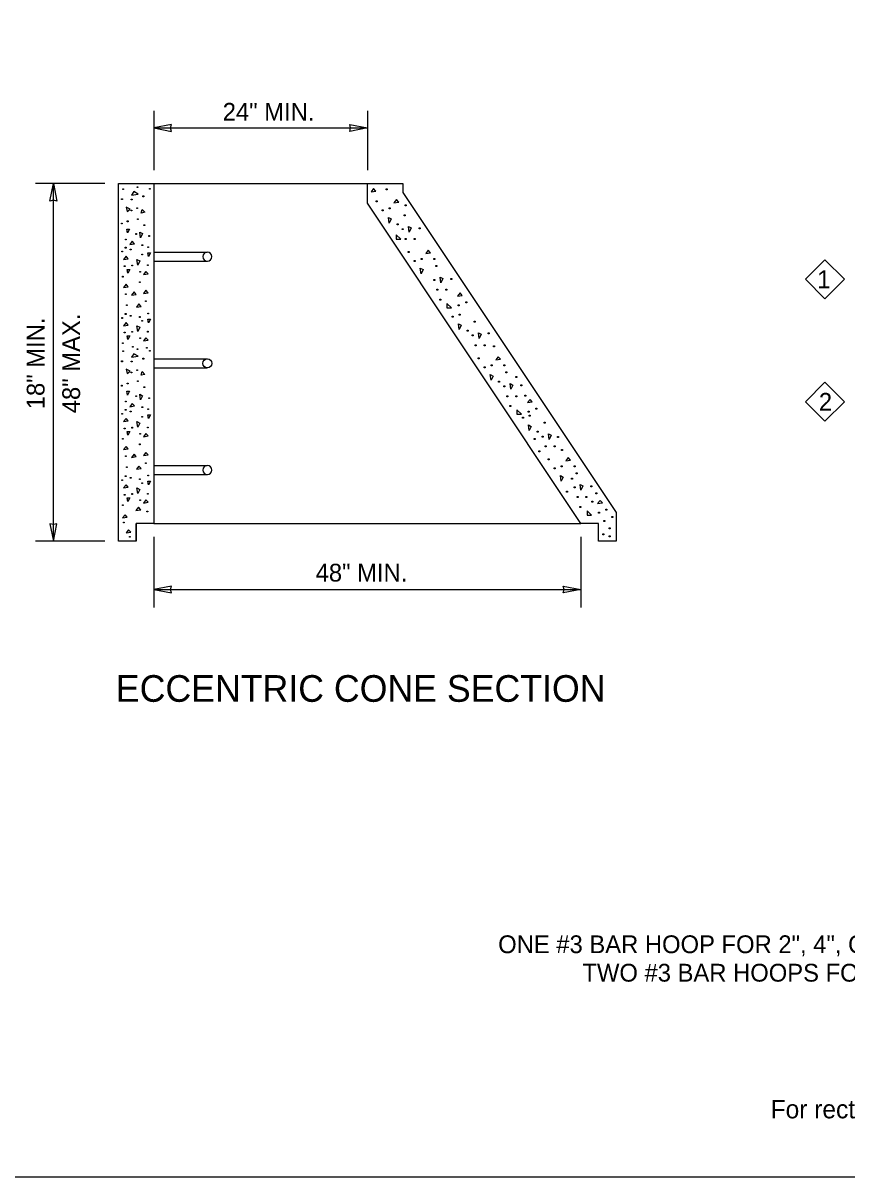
# Model space of a CAD drawing. Extents: x 99862 to 103151, y 100000 to 102076.
# Drawn here: x 100987 to 101728, y 100000 to 101038 of the extents above; entities that cross this region are included whole.
import ezdxf

# ---------------------------------------------------------------- set-up
doc = ezdxf.new("R2010")
doc.units = 0
for name, color, linetype in [('Level 1', 7, 'Continuous'), ('Level 15', 7, 'Continuous'), ('Level 17', 7, 'Continuous'), ('Level 18', 7, 'Continuous'), ('Level 20', 7, 'Continuous')]:
    doc.layers.add(name, color=color, linetype=linetype)

msp = doc.modelspace()

# ---------------------------------------------------------------- linework, layer by layer
at = {"layer": 'Level 1'}
for p, q in [((101086.4, 100885.9), (101084.4, 100882.7)), ((101084.4, 100882.7), (101090.5, 100883.6)), ((101090.5, 100883.6), (101086.4, 100885.9)), ((101079.7, 100872), (101080.6, 100868)), ((101083.3, 100870.2), (101079.7, 100872)), ((101080.6, 100868), (101083.3, 100870.2)), ((101093.1, 100866.6), (101094, 100869.8)), ((101096.3, 100867.3), (101093.1, 100866.6)), ((101094, 100869.8), (101096.3, 100867.3)), ((101086.4, 100740), (101084.4, 100736.9)), ((101090.5, 100737.8), (101086.4, 100740)), ((101084.4, 100736.9), (101090.5, 100737.8)), ((101079.7, 100726.2), (101080.6, 100722.2)), ((101083.3, 100724.4), (101079.7, 100726.2)), ((101080.6, 100722.2), (101083.3, 100724.4)), ((101093.1, 100720.8), (101094, 100724)), ((101096.3, 100721.5), (101093.1, 100720.8)), ((101094, 100724), (101096.3, 100721.5)), ((101104.6, 100527.9), (101488.6, 100527.9))]:
    msp.add_line(p, q, dxfattribs=at)
for points in [[(99862, 99999.5), (103151, 99999.5), (103151, 102075.5), (99862, 102075.5)], [(101076.6, 100888.5), (101077.3, 100888.5), (101077.3, 100887.9), (101076.6, 100887.9)], [(101089.6, 100890.3), (101090.2, 100890.3), (101090.2, 100889.7), (101089.6, 100889.7)], [(101100.5, 100888.8), (101101.2, 100888.8), (101101.2, 100888.1), (101100.5, 100888.1)], [(101302.2, 100888.6), (101299.9, 100885.7), (101304.2, 100886.3)], [(101313.6, 100888.3), (101314.5, 100888.3), (101314.5, 100887.4), (101313.6, 100887.4)], [(101075.5, 100879.4), (101076.2, 100879.4), (101076.2, 100878.7), (101075.5, 100878.7)], [(101084.2, 100879.2), (101084.9, 100879.2), (101084.9, 100878.5), (101084.2, 100878.5)], [(101094.5, 100882.1), (101095.4, 100882.1), (101095.4, 100881.2), (101094.5, 100881.2)], [(101304.6, 100877.6), (101305.5, 100877.6), (101305.5, 100876.7), (101304.6, 100876.7)], [(101322.7, 100878.7), (101320.5, 100875.8), (101324.8, 100876.5)], [(101330.6, 100874), (101331.4, 100874), (101331.4, 100873.1), (101330.6, 100873.1)], [(101084, 100869.3), (101084.6, 100869.3), (101084.6, 100868.7), (101084, 100868.7)], [(101089.1, 100871.3), (101089.8, 100871.3), (101089.8, 100870.7), (101089.1, 100870.7)], [(101310, 100869.5), (101310.9, 100869.5), (101310.9, 100868.6), (101310, 100868.6)], [(101315.6, 100862.6), (101318, 100861.3), (101316.3, 100857.5)], [(101316.2, 100871.3), (101317.1, 100871.3), (101317.1, 100870.4), (101316.2, 100870.4)], [(101329.7, 100865.1), (101330.6, 100865.1), (101330.6, 100864.2), (101329.7, 100864.2)], [(101075.3, 100857.5), (101075.9, 100857.5), (101075.9, 100856.8), (101075.3, 100856.8)], [(101080.2, 100852.1), (101082.6, 100852.1), (101080.8, 100848.8)], [(101080.6, 100859.5), (101081.3, 100859.5), (101081.3, 100858.8), (101080.6, 100858.8)], [(101089.8, 100861.5), (101090.5, 100861.5), (101090.5, 100860.8), (101089.8, 100860.8)], [(101095.6, 100856.1), (101096.3, 100856.1), (101096.3, 100855.5), (101095.6, 100855.5)], [(101323.4, 100857), (101324.3, 100857), (101324.3, 100856.1), (101323.4, 100856.1)], [(101327.9, 100852.5), (101328.8, 100852.5), (101328.8, 100851.7), (101327.9, 100851.7)], [(101333.5, 100854.6), (101335.9, 100853.2), (101334.1, 100849.4)], [(101343.1, 100853.4), (101344, 100853.4), (101344, 100852.5), (101343.1, 100852.5)], [(101079.1, 100843.2), (101079.7, 100843.2), (101079.7, 100842.5), (101079.1, 100842.5)], [(101088.2, 100848.1), (101088.9, 100848.1), (101088.9, 100847.4), (101088.2, 100847.4)], [(101091.8, 100849.4), (101094.3, 100848.1), (101092.5, 100844.3)], [(101100.1, 100846.3), (101100.7, 100846.3), (101100.7, 100845.6), (101100.1, 100845.6)], [(101322.6, 100847), (101322.6, 100843), (101326.6, 100843)], [(101330.6, 100843.6), (101331.5, 100843.6), (101331.5, 100842.7), (101330.6, 100842.7)], [(101338.6, 100843.6), (101339.5, 100843.6), (101339.5, 100842.7), (101338.6, 100842.7)], [(101075.7, 100832.2), (101076.4, 100832.2), (101076.4, 100831.6), (101075.7, 100831.6)], [(101078.8, 100835.8), (101079.5, 100835.8), (101079.5, 100835.1), (101078.8, 100835.1)], [(101085.1, 100841.2), (101082.9, 100838.3), (101087.1, 100838.9)], [(101083.3, 100834.2), (101084, 100834.2), (101084, 100833.6), (101083.3, 100833.6)], [(101093.8, 100838), (101094.5, 100838), (101094.5, 100837.4), (101093.8, 100837.4)], [(101099.2, 100836.3), (101099.8, 100836.3), (101099.8, 100835.6), (101099.2, 100835.6)], [(101333.2, 100832), (101334.1, 100832), (101334.1, 100831.1), (101333.2, 100831.1)], [(101351.4, 100833.1), (101349.1, 100830.2), (101353.4, 100830.9)], [(101079.5, 100827.8), (101077.3, 100824.9), (101081.5, 100825.5)], [(101089.3, 100824.9), (101091.8, 100823.5), (101090, 100819.7)], [(101093.6, 100829.5), (101094.3, 100829.5), (101094.3, 100828.9), (101093.6, 100828.9)], [(101099.2, 100830.9), (101101.6, 100830.9), (101099.8, 100827.5)], [(101338.6, 100823.9), (101339.5, 100823.9), (101339.5, 100823), (101338.6, 100823)], [(101344.9, 100825.7), (101345.8, 100825.7), (101345.8, 100824.8), (101344.9, 100824.8)], [(101356.5, 100825.7), (101357.4, 100825.7), (101357.4, 100824.8), (101356.5, 100824.8)], [(101077.9, 100819), (101078.6, 100819), (101078.6, 100818.4), (101077.9, 100818.4)], [(101080.4, 100815.9), (101082.9, 100815.9), (101081.1, 100812.6)], [(101084.6, 100819.7), (101085.3, 100819.7), (101085.3, 100819), (101084.6, 100819)], [(101091.8, 100814.1), (101092.5, 100814.1), (101092.5, 100813.5), (101091.8, 100813.5)], [(101097.4, 100814.1), (101095.2, 100811.2), (101099.4, 100811.9)], [(101098.7, 100819.9), (101099.4, 100819.9), (101099.4, 100819.3), (101098.7, 100819.3)], [(101344.2, 100817), (101346.7, 100815.7), (101344.9, 100811.9)], [(101358.3, 100819.5), (101359.2, 100819.5), (101359.2, 100818.6), (101358.3, 100818.6)], [(101076.4, 100809.7), (101077, 100809.7), (101077, 100809), (101076.4, 100809)], [(101079.5, 100802.5), (101077.3, 100799.6), (101081.5, 100800.3)], [(101091.6, 100804.7), (101092.2, 100804.7), (101092.2, 100804), (101091.6, 100804)], [(101356.5, 100806.9), (101357.4, 100806.9), (101357.4, 100806), (101356.5, 100806)], [(101362.1, 100808.9), (101364.5, 100807.6), (101362.8, 100803.8)], [(101371.7, 100807.8), (101372.6, 100807.8), (101372.6, 100806.9), (101371.7, 100806.9)], [(101079.1, 100793.9), (101079.7, 100793.9), (101079.7, 100793.3), (101079.1, 100793.3)], [(101086.7, 100795.6), (101084.4, 100792.7), (101088.7, 100793.3)], [(101097.4, 100797.1), (101095.2, 100794.2), (101099.4, 100794.9)], [(101359.2, 100798), (101360.1, 100798), (101360.1, 100797.1), (101359.2, 100797.1)], [(101367.2, 100798), (101368.1, 100798), (101368.1, 100797.1), (101367.2, 100797.1)], [(101380, 100794.7), (101377.7, 100791.8), (101382, 100792.4)], [(101080, 100784.1), (101080.6, 100784.1), (101080.6, 100783.4), (101080, 100783.4)], [(101091.1, 100784.8), (101088.9, 100781.9), (101093.1, 100782.6)], [(101096.9, 100787.7), (101097.6, 100787.7), (101097.6, 100787), (101096.9, 100787)], [(101361.9, 100789.1), (101362.8, 100789.1), (101362.8, 100788.2), (101361.9, 100788.2)], [(101368.2, 100785.3), (101368.2, 100781.3), (101372.2, 100781.3)], [(101378.4, 100784.1), (101379.3, 100784.1), (101379.3, 100783.2), (101378.4, 100783.2)], [(101385.1, 100786.8), (101386, 100786.8), (101386, 100785.9), (101385.1, 100785.9)], [(101075.7, 100772.5), (101076.4, 100772.5), (101076.4, 100771.8), (101075.7, 100771.8)], [(101078.8, 100776.1), (101079.5, 100776.1), (101079.5, 100775.4), (101078.8, 100775.4)], [(101083.3, 100774.5), (101084, 100774.5), (101084, 100773.9), (101083.3, 100773.9)], [(101091.6, 100773.4), (101092.2, 100773.4), (101092.2, 100772.7), (101091.6, 100772.7)], [(101093.6, 100769.8), (101094.3, 100769.8), (101094.3, 100769.2), (101093.6, 100769.2)], [(101099.2, 100776.5), (101099.8, 100776.5), (101099.8, 100775.9), (101099.2, 100775.9)], [(101099.2, 100771.2), (101101.6, 100771.2), (101099.8, 100767.8)], [(101373, 100773.9), (101373.9, 100773.9), (101373.9, 100773), (101373, 100773)], [(101379.3, 100775.6), (101380.2, 100775.6), (101380.2, 100774.7), (101379.3, 100774.7)], [(101392.7, 100769.4), (101393.6, 100769.4), (101393.6, 100768.5), (101392.7, 100768.5)], [(101079.5, 100768), (101077.3, 100765.1), (101081.5, 100765.8)], [(101077.9, 100759.3), (101078.6, 100759.3), (101078.6, 100758.7), (101077.9, 100758.7)], [(101084.6, 100760), (101085.3, 100760), (101085.3, 100759.3), (101084.6, 100759.3)], [(101089.3, 100765.1), (101091.8, 100763.8), (101090, 100760)], [(101098.7, 100760.2), (101099.4, 100760.2), (101099.4, 100759.5), (101098.7, 100759.5)], [(101378.6, 100766.9), (101381.1, 100765.6), (101379.3, 100761.8)], [(101386.4, 100761.3), (101387.3, 100761.3), (101387.3, 100760.4), (101386.4, 100760.4)], [(101396.5, 100758.9), (101399, 100757.5), (101397.2, 100753.7)], [(101405.2, 100758.7), (101406.1, 100758.7), (101406.1, 100757.8), (101405.2, 100757.8)], [(101076.4, 100749.9), (101077, 100749.9), (101077, 100749.3), (101076.4, 100749.3)], [(101080.4, 100756.2), (101082.9, 100756.2), (101081.1, 100752.8)], [(101091.8, 100754.4), (101092.5, 100754.4), (101092.5, 100753.7), (101091.8, 100753.7)], [(101097.4, 100754.4), (101095.2, 100751.5), (101099.4, 100752.2)], [(101390.9, 100756.9), (101391.8, 100756.9), (101391.8, 100756), (101390.9, 100756)], [(101076.6, 100742.7), (101077.3, 100742.7), (101077.3, 100742.1), (101076.6, 100742.1)], [(101085.3, 100746.5), (101086, 100746.5), (101086, 100745.9), (101085.3, 100745.9)], [(101089.6, 100744.5), (101090.2, 100744.5), (101090.2, 100743.8), (101089.6, 100743.8)], [(101097.8, 100745.6), (101098.5, 100745.6), (101098.5, 100745), (101097.8, 100745)], [(101100.5, 100742.9), (101101.2, 100742.9), (101101.2, 100742.3), (101100.5, 100742.3)], [(101393.6, 100747.9), (101394.5, 100747.9), (101394.5, 100747), (101393.6, 100747)], [(101401.7, 100747.9), (101402.6, 100747.9), (101402.6, 100747), (101401.7, 100747)], [(101410.2, 100747), (101411, 100747), (101411, 100746.1), (101410.2, 100746.1)], [(101075.5, 100733.6), (101076.2, 100733.6), (101076.2, 100732.9), (101075.5, 100732.9)], [(101084.2, 100733.3), (101084.9, 100733.3), (101084.9, 100732.7), (101084.2, 100732.7)], [(101094.5, 100736.2), (101095.4, 100736.2), (101095.4, 100735.3), (101094.5, 100735.3)], [(101396.3, 100736.3), (101397.2, 100736.3), (101397.2, 100735.4), (101396.3, 100735.4)], [(101401.6, 100728.2), (101402.5, 100728.2), (101402.5, 100727.3), (101401.6, 100727.3)], [(101407.9, 100730), (101408.8, 100730), (101408.8, 100729.1), (101407.9, 100729.1)], [(101414.4, 100737.4), (101412.2, 100734.5), (101416.4, 100735.2)], [(101419.5, 100730), (101420.4, 100730), (101420.4, 100729.1), (101419.5, 100729.1)], [(101084, 100723.5), (101084.6, 100723.5), (101084.6, 100722.8), (101084, 100722.8)], [(101089.1, 100725.5), (101089.8, 100725.5), (101089.8, 100724.9), (101089.1, 100724.9)], [(101407.2, 100721.3), (101409.7, 100720), (101407.9, 100716.2)], [(101421.3, 100723.8), (101422.2, 100723.8), (101422.2, 100722.9), (101421.3, 100722.9)], [(101430.3, 100719.7), (101431.2, 100719.7), (101431.2, 100718.8), (101430.3, 100718.8)], [(101075.3, 100711.7), (101075.9, 100711.7), (101075.9, 100711), (101075.3, 100711)], [(101080.6, 100713.7), (101081.3, 100713.7), (101081.3, 100713), (101080.6, 100713)], [(101089.8, 100715.7), (101090.5, 100715.7), (101090.5, 100715), (101089.8, 100715)], [(101095.6, 100710.3), (101096.3, 100710.3), (101096.3, 100709.7), (101095.6, 100709.7)], [(101414.6, 100715.3), (101415.5, 100715.3), (101415.5, 100714.4), (101414.6, 100714.4)], [(101419.5, 100711.3), (101420.4, 100711.3), (101420.4, 100710.4), (101419.5, 100710.4)], [(101425.1, 100713.3), (101427.6, 100711.9), (101425.8, 100708.1)], [(101434.7, 100712.1), (101435.6, 100712.1), (101435.6, 100711.3), (101434.7, 100711.3)], [(101079.1, 100697.4), (101079.7, 100697.4), (101079.7, 100696.7), (101079.1, 100696.7)], [(101080.2, 100706.3), (101082.6, 100706.3), (101080.8, 100702.9)], [(101088.2, 100702.3), (101088.9, 100702.3), (101088.9, 100701.6), (101088.2, 100701.6)], [(101091.8, 100703.6), (101094.3, 100702.3), (101092.5, 100698.5)], [(101100.1, 100700.5), (101100.7, 100700.5), (101100.7, 100699.8), (101100.1, 100699.8)], [(101422.2, 100702.3), (101423.1, 100702.3), (101423.1, 100701.4), (101422.2, 100701.4)], [(101430.3, 100702.3), (101431.2, 100702.3), (101431.2, 100701.4), (101430.3, 100701.4)], [(101438.3, 100702.7), (101439.2, 100702.7), (101439.2, 100701.8), (101438.3, 100701.8)], [(101443, 100699), (101440.8, 100696.1), (101445, 100696.7)], [(101075.7, 100686.4), (101076.4, 100686.4), (101076.4, 100685.7), (101075.7, 100685.7)], [(101078.8, 100690), (101079.5, 100690), (101079.5, 100689.3), (101078.8, 100689.3)], [(101085.1, 100695.3), (101082.9, 100692.4), (101087.1, 100693.1)], [(101083.3, 100688.4), (101084, 100688.4), (101084, 100687.8), (101083.3, 100687.8)], [(101093.8, 100692.2), (101094.5, 100692.2), (101094.5, 100691.6), (101093.8, 100691.6)], [(101099.2, 100690.4), (101099.8, 100690.4), (101099.8, 100689.8), (101099.2, 100689.8)], [(101424.9, 100693.4), (101425.8, 100693.4), (101425.8, 100692.5), (101424.9, 100692.5)], [(101431.2, 100689.7), (101431.2, 100685.6), (101435.3, 100685.6)], [(101441.4, 100688.5), (101442.3, 100688.5), (101442.3, 100687.6), (101441.4, 100687.6)], [(101448.2, 100691.1), (101449, 100691.1), (101449, 100690.2), (101448.2, 100690.2)], [(101079.5, 100681.9), (101077.3, 100679), (101081.5, 100679.7)], [(101089.3, 100679), (101091.8, 100677.7), (101090, 100673.9)], [(101093.6, 100683.7), (101094.3, 100683.7), (101094.3, 100683.1), (101093.6, 100683.1)], [(101099.2, 100685.1), (101101.6, 100685.1), (101099.8, 100681.7)], [(101436.1, 100683), (101437, 100683), (101437, 100682.1), (101436.1, 100682.1)], [(101441.7, 100676.1), (101444.1, 100674.7), (101442.3, 100670.9)], [(101442.3, 100684.8), (101443.2, 100684.8), (101443.2, 100683.9), (101442.3, 100683.9)], [(101455.8, 100678.5), (101456.6, 100678.5), (101456.6, 100677.7), (101455.8, 100677.7)], [(101077.9, 100673.2), (101078.6, 100673.2), (101078.6, 100672.6), (101077.9, 100672.6)], [(101080.4, 100670.1), (101082.9, 100670.1), (101081.1, 100666.7)], [(101084.6, 100673.9), (101085.3, 100673.9), (101085.3, 100673.2), (101084.6, 100673.2)], [(101091.8, 100668.3), (101092.5, 100668.3), (101092.5, 100667.6), (101091.8, 100667.6)], [(101097.4, 100668.3), (101095.2, 100665.4), (101099.4, 100666.1)], [(101098.7, 100674.1), (101099.4, 100674.1), (101099.4, 100673.5), (101098.7, 100673.5)], [(101449.5, 100670.5), (101450.4, 100670.5), (101450.4, 100669.6), (101449.5, 100669.6)], [(101454, 100666), (101454.9, 100666), (101454.9, 100665.1), (101454, 100665.1)], [(101459.6, 100668), (101462, 100666.7), (101460.2, 100662.9)], [(101467.8, 100665.6), (101468.7, 100665.6), (101468.7, 100664.7), (101467.8, 100664.7)], [(101076.4, 100663.8), (101077, 100663.8), (101077, 100663.2), (101076.4, 100663.2)], [(101079.5, 100656.7), (101077.3, 100653.8), (101081.5, 100654.4)], [(101091.6, 100658.9), (101092.2, 100658.9), (101092.2, 100658.2), (101091.6, 100658.2)], [(101446.8, 100663.8), (101447.7, 100663.8), (101447.7, 100662.9), (101446.8, 100662.9)], [(101456.6, 100657.1), (101457.5, 100657.1), (101457.5, 100656.2), (101456.6, 100656.2)], [(101464.7, 100657.1), (101465.6, 100657.1), (101465.6, 100656.2), (101464.7, 100656.2)], [(101079.1, 100648.1), (101079.7, 100648.1), (101079.7, 100647.5), (101079.1, 100647.5)], [(101086.7, 100649.7), (101084.4, 100646.8), (101088.7, 100647.5)], [(101097.4, 100651.3), (101095.2, 100648.4), (101099.4, 100649.1)], [(101450.8, 100652.6), (101451.7, 100652.6), (101451.7, 100651.7), (101450.8, 100651.7)], [(101459.3, 100645.5), (101460.2, 100645.5), (101460.2, 100644.6), (101459.3, 100644.6)], [(101471.4, 100653.9), (101472.3, 100653.9), (101472.3, 100653.1), (101471.4, 100653.1)], [(101477.4, 100646.6), (101475.2, 100643.7), (101479.5, 100644.3)], [(101080, 100638.3), (101080.6, 100638.3), (101080.6, 100637.6), (101080, 100637.6)], [(101091.1, 100639), (101088.9, 100636.1), (101093.1, 100636.8)], [(101096.9, 100641.9), (101097.6, 100641.9), (101097.6, 100641.2), (101096.9, 100641.2)], [(101464.7, 100637.4), (101465.6, 100637.4), (101465.6, 100636.5), (101464.7, 100636.5)], [(101471, 100639.2), (101471.8, 100639.2), (101471.8, 100638.3), (101471, 100638.3)], [(101482.6, 100639.2), (101483.5, 100639.2), (101483.5, 100638.3), (101482.6, 100638.3)], [(101075.7, 100626.7), (101076.4, 100626.7), (101076.4, 100626), (101075.7, 100626)], [(101078.8, 100630.3), (101079.5, 100630.3), (101079.5, 100629.6), (101078.8, 100629.6)], [(101083.3, 100628.7), (101084, 100628.7), (101084, 100628), (101083.3, 100628)], [(101091.6, 100627.5), (101092.2, 100627.5), (101092.2, 100626.9), (101091.6, 100626.9)], [(101093.6, 100624), (101094.3, 100624), (101094.3, 100623.3), (101093.6, 100623.3)], [(101099.2, 100630.7), (101099.8, 100630.7), (101099.8, 100630.1), (101099.2, 100630.1)], [(101099.2, 100625.4), (101101.6, 100625.4), (101099.8, 100622)], [(101470.3, 100630.5), (101472.7, 100629.1), (101471, 100625.3)], [(101480.4, 100628), (101481.2, 100628), (101481.2, 100627.1), (101480.4, 100627.1)], [(101484.4, 100632.9), (101485.3, 100632.9), (101485.3, 100632), (101484.4, 100632)], [(101079.5, 100622.2), (101077.3, 100619.3), (101081.5, 100620)], [(101077.9, 100613.5), (101078.6, 100613.5), (101078.6, 100612.8), (101077.9, 100612.8)], [(101084.6, 100614.2), (101085.3, 100614.2), (101085.3, 100613.5), (101084.6, 100613.5)], [(101089.3, 100619.3), (101091.8, 100618), (101090, 100614.2)], [(101098.7, 100614.4), (101099.4, 100614.4), (101099.4, 100613.7), (101098.7, 100613.7)], [(101475.9, 100616.4), (101476.8, 100616.4), (101476.8, 100615.5), (101475.9, 100615.5)], [(101482.6, 100620.4), (101483.5, 100620.4), (101483.5, 100619.5), (101482.6, 100619.5)], [(101488.2, 100622.4), (101490.6, 100621.1), (101488.8, 100617.3)], [(101497.8, 100621.3), (101498.7, 100621.3), (101498.7, 100620.4), (101497.8, 100620.4)], [(101502.3, 100615), (101503.2, 100615), (101503.2, 100614.1), (101502.3, 100614.1)], [(101076.4, 100604.1), (101077, 100604.1), (101077, 100603.5), (101076.4, 100603.5)], [(101080.4, 100610.4), (101082.9, 100610.4), (101081.1, 100607)], [(101091.8, 100608.6), (101092.5, 100608.6), (101092.5, 100607.9), (101091.8, 100607.9)], [(101097.4, 100608.6), (101095.2, 100605.7), (101099.4, 100606.4)], [(101485.3, 100611.5), (101486.2, 100611.5), (101486.2, 100610.6), (101485.3, 100610.6)], [(101493.3, 100611.5), (101494.2, 100611.5), (101494.2, 100610.6), (101493.3, 100610.6)], [(101498.7, 100607.4), (101499.6, 100607.4), (101499.6, 100606.5), (101498.7, 100606.5)], [(101506.1, 100608.1), (101503.8, 100605.2), (101508.1, 100605.9)], [(101078.6, 100595.2), (101076.4, 100592.3), (101080.6, 100592.9)], [(101090.7, 100601.9), (101088.4, 100599), (101092.7, 100599.6)], [(101098.3, 100598.5), (101099, 100598.5), (101099, 100597.8), (101098.3, 100597.8)], [(101487.9, 100602.5), (101488.8, 100602.5), (101488.8, 100601.6), (101487.9, 100601.6)], [(101494.3, 100598.8), (101494.3, 100594.8), (101498.3, 100594.8)], [(101504.5, 100597.6), (101505.4, 100597.6), (101505.4, 100596.7), (101504.5, 100596.7)], [(101511.2, 100600.3), (101512.1, 100600.3), (101512.1, 100599.4), (101511.2, 100599.4)], [(101516.6, 100593.5), (101517.5, 100593.5), (101517.5, 100592.6), (101516.6, 100592.6)], [(101077.3, 100588.6), (101077.9, 100588.6), (101077.9, 100587.9), (101077.3, 100587.9)], [(101509.4, 100590), (101510.3, 100590), (101510.3, 100589.1), (101509.4, 100589.1)], [(101514.3, 100583.3), (101515.2, 100583.3), (101515.2, 100582.4), (101514.3, 100582.4)], [(101081.7, 100581.7), (101079.5, 100578.8), (101083.8, 100579.5)], [(101082.6, 100575.6), (101083.3, 100575.6), (101083.3, 100575), (101082.6, 100575)], [(101508.5, 100577.9), (101509.4, 100577.9), (101509.4, 100577), (101508.5, 100577)], [(101514.3, 100576.1), (101515.2, 100576.1), (101515.2, 100575.2), (101514.3, 100575.2)]]:
    msp.add_lwpolyline(points, close=True, dxfattribs=at)
at = {"layer": 'Level 15'}
for p, q in [((101060.6, 100893.2), (100998.2, 100893.2)), ((101014.2, 100571.4), (101014.2, 100893.2)), ((101104.6, 100575.4), (101104.6, 100511.9)), ((101488.6, 100575.4), (101488.6, 100511.9)), ((101060.6, 100571.4), (100998.2, 100571.4))]:
    msp.add_line(p, q, dxfattribs=at)
for points in [[(101104.6, 100943.2), (101120.4, 100940.1), (101119.6, 100943.2), (101120.4, 100946.2)], [(101296.6, 100943.2), (101280.9, 100940.1), (101281.6, 100943.2), (101280.9, 100946.2)], [(101014.2, 100893.2), (101017.3, 100877.4), (101014.2, 100878.2), (101011.1, 100877.4)], [(101014.2, 100571.4), (101017.3, 100587.1), (101014.2, 100586.4), (101011.1, 100587.1)], [(101104.6, 100527.9), (101120.4, 100524.8), (101119.6, 100527.9), (101120.4, 100531)], [(101488.6, 100527.9), (101472.9, 100524.8), (101473.6, 100527.9), (101472.9, 100531)]]:
    msp.add_lwpolyline(points, close=True, dxfattribs=at)
at = {"layer": 'Level 17'}
for p, q in [((101104.6, 100893.2), (101296.6, 100893.2)), ((101088.6, 100571.4), (101088.6, 100587.4)), ((101104.6, 100587.4), (101488.6, 100587.4))]:
    msp.add_line(p, q, dxfattribs=at)
for points in [[(101072.6, 100893.2), (101104.6, 100893.2), (101104.6, 100587.4), (101088.6, 100587.4), (101088.6, 100571.4), (101072.6, 100571.4), (101072.6, 100893.2)], [(101296.6, 100893.2), (101328.6, 100893.2), (101328.6, 100885.1), (101520.6, 100597.1), (101520.6, 100571.4), (101504.6, 100571.4), (101504.6, 100587.4), (101488.6, 100587.4), (101296.6, 100875.4), (101296.6, 100893.2)]]:
    msp.add_lwpolyline(points, dxfattribs=at)
at = {"layer": 'Level 18'}
for p, q in [((101104.6, 100831.4), (101152.6, 100831.4)), ((101104.6, 100823.4), (101152.6, 100823.4)), ((101104.6, 100735.4), (101152.6, 100735.4)), ((101104.6, 100727.4), (101152.6, 100727.4)), ((101104.6, 100639.4), (101152.6, 100639.4)), ((101104.6, 100631.4), (101152.6, 100631.4))]:
    msp.add_line(p, q, dxfattribs=at)
msp.add_circle((101152.7, 100731.4), 4, dxfattribs=at)
for centre in [(101152.7, 100827.4), (101152.7, 100635.4)]:
    msp.add_arc(centre, 4, 270.07, 269.7846, dxfattribs=at)
at = {"layer": 'Level 20'}
for p, q in [((101104.6, 100958.7), (101104.6, 100905.2)), ((101296.6, 100958.7), (101296.6, 100905.2)), ((101104.6, 100943.2), (101296.6, 100943.2))]:
    msp.add_line(p, q, dxfattribs=at)
for points in [[(101708.2, 100824.6), (101725.8, 100807), (101708.2, 100789.5), (101690.7, 100807)], [(101708.2, 100714.4), (101725.8, 100696.8), (101708.2, 100679.3), (101690.7, 100696.8)]]:
    msp.add_lwpolyline(points, close=True, dxfattribs=at)

# ---------------------------------------------------------------- texts
for s, height, p in [('24" MIN.', 16, (101166.5, 100949.7)), ('1', 16, (101701.3, 100799)), ('2', 16, (101702.8, 100688.8)), ('48" MIN.', 16, (101250.1, 100535.1)), ('ECCENTRIC CONE SECTION', 24, (101070.4, 100426.9)), ('ONE #3 BAR HOOP FOR 2", 4", OR 6" (IN)', 16, (101414.3, 100200.8)), ('TWO #3 BAR HOOPS FOR 12" (IN)', 16, (101490.1, 100175.2)), ('For rectangular and circular adjustment sections, approved alternate material', 16.5, (101659.4, 100052.2))]:
    msp.add_text(s, height=height, dxfattribs=at).set_placement(p)
for s, p in [('18" MIN.', (101006.2, 100690.1)), ('48" MAX.', (101038.2, 100686.5))]:
    msp.add_text(s, height=16, rotation=90, dxfattribs=at).set_placement(p)

doc.saveas('drawing.dxf')
